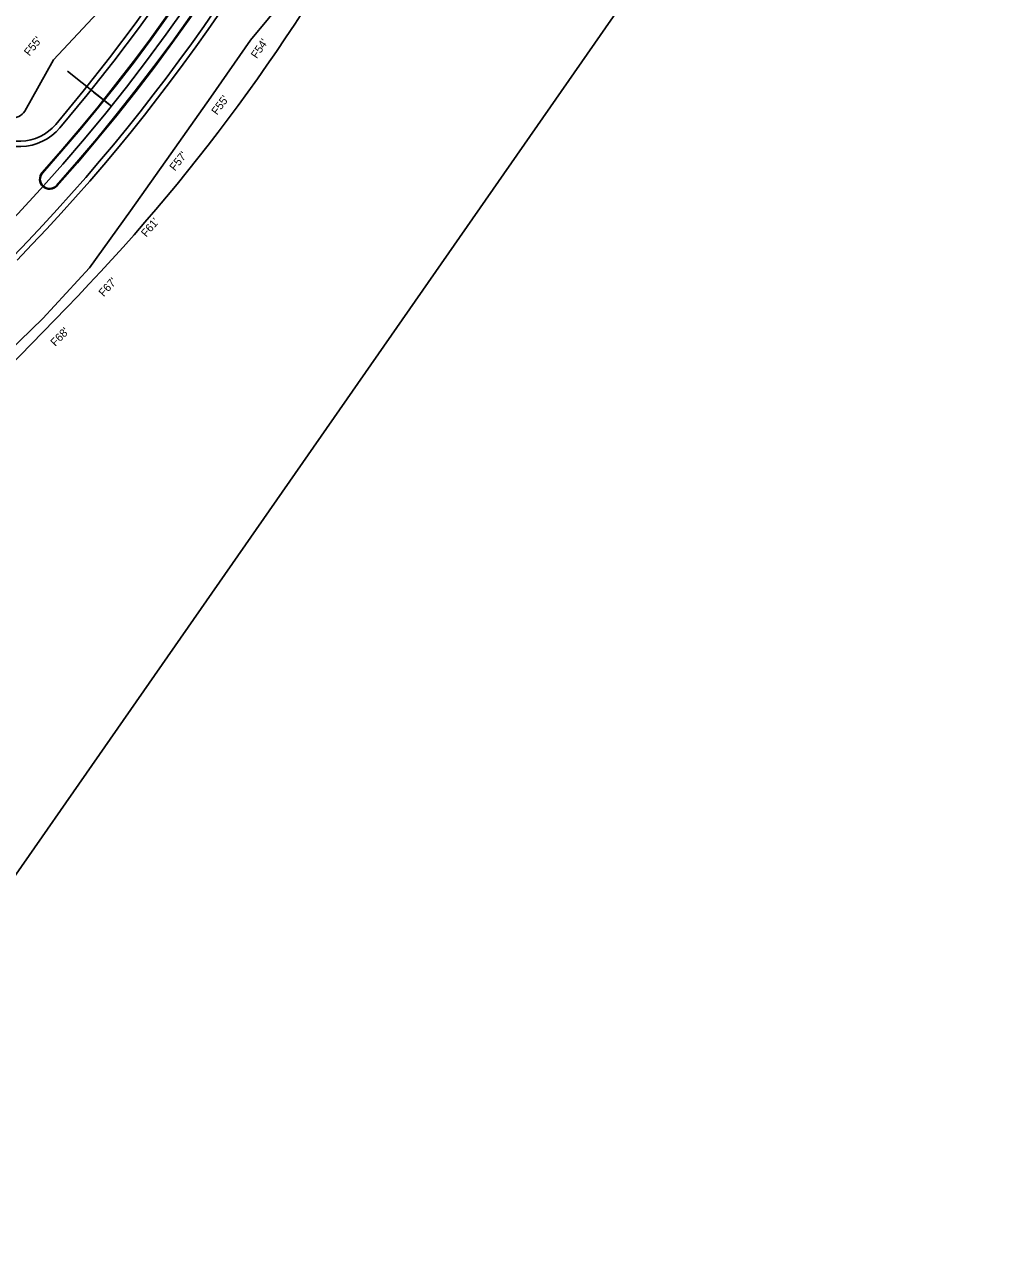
# Model space of a CAD drawing. Extents: x 2358865 to 2362945, y 393485 to 404880.
# Drawn here: x 2361612 to 2362345, y 399242 to 400160 of the extents above; entities that cross this region are included whole.
import ezdxf

# ---------------------------------------------------------------- set-up
doc = ezdxf.new("R2010")
doc.units = 0
for name, color, linetype in [('CL', 7, 'Continuous'), ('Level 11', 7, 'Continuous'), ('Level 19', 7, 'Continuous'), ('Level 25', 7, 'Continuous'), ('Level 27', 7, 'Continuous'), ('Level 30', 7, 'Continuous'), ('Level 37', 7, 'Continuous'), ('Level 39', 7, 'Continuous'), ('Level 41', 7, 'Continuous'), ('Level 48', 7, 'Continuous'), ('Level 51', 7, 'Continuous'), ('Level 52', 7, 'Continuous'), ('Level 53', 7, 'Continuous'), ('Level 63', 7, 'Continuous')]:
    doc.layers.add(name, color=color, linetype=linetype)

msp = doc.modelspace()

# ---------------------------------------------------------------- linework, layer by layer
at = {"layer": 'CL'}
msp.add_arc((2360608.55, 400955.34), 1370, 315.75191, 87.32696, dxfattribs=at)
at = {"layer": 'Level 11'}
for centre, radius, start, end in [((2360608.55, 400955.34), 1346.5, 319.72072, 43.50459), ((2360608.55, 400955.34), 1393.5, 315.75191, 357.7915), ((2361608.34, 400108.08), 36, 224.16525, 319.72072)]:
    msp.add_arc(centre, radius, start, end, dxfattribs=at)
at = {"layer": 'Level 19'}
for centre, radius, start, end in [((2360608.55, 400955.34), 1350.5, 319.72072, 43.50459), ((2360608.55, 400955.34), 1389.5, 315.75191, 357.79636), ((2361608.34, 400108.08), 40, 224.16525, 319.72072)]:
    msp.add_arc(centre, radius, start, end, dxfattribs=at)
at = {"layer": 'Level 25'}
msp.add_line((2361677.45, 400098.39), (2361673.55, 400101.52), dxfattribs=at)
at = {"layer": 'Level 27'}
msp.add_line((2361421.89, 399719.41), (2361643.64, 399947.06), dxfattribs=at)
msp.add_arc((2360608.55, 400955.34), 1445, 315.75191, 347.27779, dxfattribs=at)
at = {"layer": 'Level 30'}
msp.add_line((2361677.45, 400098.39), (2361670.82, 400103.71), dxfattribs=at)
at = {"layer": 'Level 37'}
for centre, radius, start, end in [((2360608.55, 400955.34), 1377, 318.28168, 18.55185), ((2360608.55, 400955.34), 1377.5, 318.28168, 18.55185), ((2360608.55, 400955.34), 1362.5, 318.28168, 15.37844), ((2360608.55, 400955.34), 1363, 318.28168, 15.37844), ((2361631.16, 400043.69), 7.5, 138.00225, 318.00225), ((2361631.16, 400043.69), 7, 138.00225, 318.00225)]:
    msp.add_arc(centre, radius, start, end, dxfattribs=at)
at = {"layer": 'Level 39'}
msp.add_line((2361677.45, 400098.39), (2361664.19, 400109.02), dxfattribs=at)
at = {"layer": 'Level 41'}
msp.add_line((2361677.45, 400098.39), (2361644.68, 400124.66), dxfattribs=at)
at = {"layer": 'Level 48'}
for centre, radius, start, end in [((2360608.55, 400955.34), 1377, 318.28168, 18.55185), ((2360608.55, 400955.34), 1363, 318.28168, 15.37844), ((2361631.16, 400043.64), 7, 138.28168, 318.28168)]:
    msp.add_arc(centre, radius, start, end, dxfattribs=at)
at = {"layer": 'Level 51'}
for p, q in [((2361634.09, 400133.12), (2361667.06, 400168.38)), ((2361752, 400105.3), (2361781.76, 400147.94)), ((2361612.58, 400094.78), (2361634.09, 400133.12)), ((2361722.08, 400062.66), (2361752, 400105.3)), ((2361691.87, 400019.94), (2361722.08, 400062.66)), ((2361661.05, 399977.3), (2361691.87, 400019.94)), ((2361626.04, 399939.35), (2361661.05, 399977.3)), ((2361590.16, 399904.5), (2361626.04, 399939.35))]:
    msp.add_line(p, q, dxfattribs=at)
msp.add_arc((2361603.86, 400099.68), 10, 259.69079, 330.70188, dxfattribs=at)
at = {"layer": 'Level 52'}
msp.add_line((2361781.76, 400147.94), (2361815.17, 400188.29), dxfattribs=at)
at = {"layer": 'Level 63'}
msp.add_lwpolyline([(2361523.36, 400803.05), (2360833.34, 399804.11), (2361123.95, 399521.03), (2361123.95, 399521.03), (2361410.48, 399241.92), (2362305.58, 400527.88), (2362344.68, 400666.91), (2362107.55, 400706.22), (2362028.41, 400719.34)], close=True, dxfattribs=at)

# ---------------------------------------------------------------- texts
at = {"layer": 'Level 53'}
for s, rotation, p in [("F55'", 51.2807, (2361616.07, 400135.57)), ("F54'", 55.46319, (2361786.49, 400133.65)), ("F55'", 53.37192, (2361756.71, 400091.36)), ("F57'", 51.2807, (2361725.12, 400049.41)), ("F61'", 49.18952, (2361703.63, 399999.84)), ("F67'", 47.09838, (2361671.64, 399955.21)), ("F68'", 45.75191, (2361635.49, 399917.92))]:
    msp.add_text(s, height=6, rotation=rotation, dxfattribs=at).set_placement(p)

doc.saveas('drawing.dxf')
